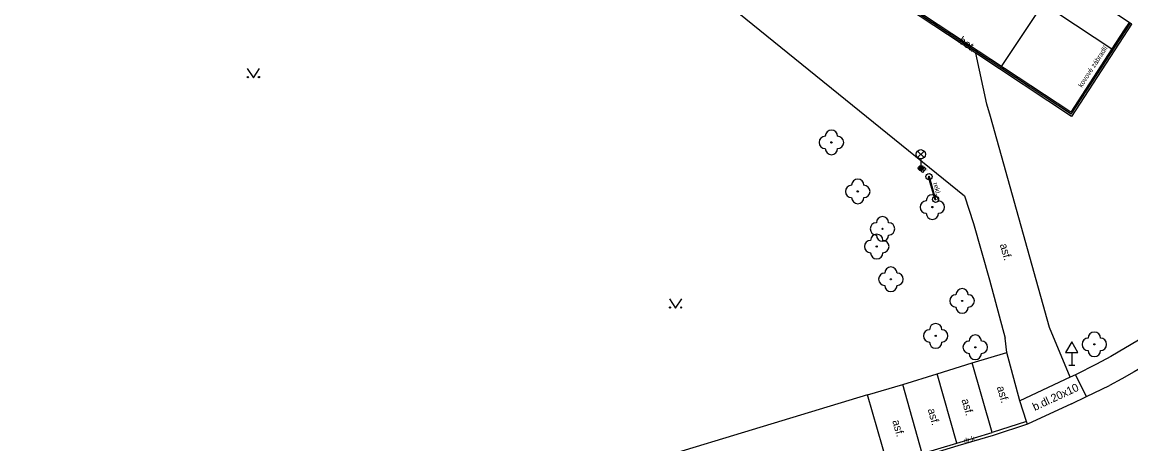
# Model space of a CAD drawing. Extents: x -598233 to -596890, y -1157848 to -1156431.
# Drawn here: x -597129.4 to -597039.3, y -1157222.9 to -1157188.6 of the extents above; entities that cross this region are included whole.
import ezdxf

# ---------------------------------------------------------------- set-up
doc = ezdxf.new("R2010")
doc.units = 0
for name, color, linetype in [('Level 10', 7, 'Continuous'), ('Level 11', 7, 'Continuous'), ('Level 22', 7, 'Continuous'), ('Level 25', 7, 'Continuous'), ('Level 33', 7, 'Continuous'), ('Level 34', 7, 'Continuous'), ('Level 36', 7, 'Continuous'), ('Level 40', 7, 'Continuous'), ('Level 42', 7, 'Continuous'), ('Level 5', 7, 'Continuous'), ('Level 7', 7, 'Continuous'), ('Level 9', 7, 'Continuous')]:
    doc.layers.add(name, color=color, linetype=linetype)

msp = doc.modelspace()

# ---------------------------------------------------------------- linework, layer by layer
at = {"layer": 'Level 10'}
for points in [[(-597060.71, -1157218.89), (-597057.85, -1157218.05), (-597055.05, -1157217.18), (-597052.2, -1157216.29), (-597049.38, -1157215.44)], [(-597044.13, -1157219.62), (-597047.7, -1157221.27), (-597047.78, -1157221.03), (-597048.32, -1157219.36), (-597049.38, -1157215.44)], [(-597038.06, -1157216.43), (-597039.05, -1157217.01), (-597040.04, -1157217.57), (-597041.05, -1157218.12)], [(-597044.13, -1157219.62), (-597042.91, -1157219.01), (-597041.05, -1157218.12)], [(-597060.71, -1157218.89), (-597086.42, -1157226.67), (-597120.23, -1157237.01)]]:
    msp.add_lwpolyline(points, dxfattribs=at)
at = {"layer": 'Level 11'}
for points in [[(-597144.73, -1157124.44), (-597135.06, -1157131.08), (-597109.67, -1157149.04), (-597101.08, -1157155.85), (-597100.46, -1157157.26), (-597101.39, -1157159.08), (-597101.51, -1157160.7), (-597101.1599, -1157162.15), (-597100.42, -1157163.42), (-597099.45, -1157164.7), (-597098.03, -1157166.15), (-597052.84, -1157202.74), (-597052.1, -1157204.97)], [(-597044.13, -1157196.28), (-597051.9, -1157191.16), (-597073.42, -1157176.98), (-597094.27, -1157163.14), (-597089.29, -1157155.68)], [(-597090.51, -1157157.96), (-597077.69, -1157166.4), (-597066.07, -1157174.11), (-597054.01, -1157182.08), (-597040.86, -1157190.8)], [(-597039.25, -1157188.79), (-597044.13, -1157196.28)], [(-597045.91, -1157213.41), (-597050.72, -1157196.29), (-597051, -1157195.3), (-597051.9, -1157191.16)], [(-597056.23, -1157200.84), (-597056.6, -1157200.5), (-597056.33, -1157200.28), (-597055.98, -1157200.5), (-597056.23, -1157200.84)], [(-597055.71, -1157201.17), (-597055.77, -1157201.19), (-597055.24, -1157203.03), (-597055.18, -1157203.02)], [(-597052.1, -1157204.97), (-597050.8, -1157209.55), (-597049.52, -1157214.29)], [(-597044.25, -1157217.44), (-597045.91, -1157213.41)], [(-597049.38, -1157215.44), (-597049.52, -1157214.29)], [(-597038.68, -1157214.45), (-597040.94, -1157215.78), (-597042.1, -1157216.39)], [(-597050.58, -1157221.93), (-597052.2, -1157216.29)], [(-597042.1, -1157216.39), (-597043.81, -1157217.25), (-597044.25, -1157217.44)], [(-597053.44, -1157222.79), (-597055.05, -1157217.18)], [(-597044.25, -1157217.44), (-597048.32, -1157219.36)], [(-597042.91, -1157219.01), (-597043.81, -1157217.25)], [(-597056.27, -1157223.65), (-597057.85, -1157218.05)], [(-597059.01, -1157224.75), (-597059.08, -1157224.51), (-597060.71, -1157218.89)], [(-597047.7, -1157221.27), (-597050.51, -1157222.17), (-597053.37, -1157223.03), (-597056.2, -1157223.89), (-597059.01, -1157224.75)], [(-597047.78, -1157221.03), (-597050.58, -1157221.93)], [(-597059.08, -1157224.51), (-597056.27, -1157223.65), (-597053.44, -1157222.79), (-597050.58, -1157221.93)]]:
    msp.add_lwpolyline(points, dxfattribs=at)
at = {"layer": 'Level 22'}
for centre in [(-597063.64, -1157198.39), (-597061.5, -1157202.37), (-597055.44, -1157203.64), (-597059.49, -1157205.41), (-597059.96, -1157206.84), (-597058.81, -1157209.5), (-597053.02, -1157211.26), (-597055.17, -1157214.09), (-597051.95, -1157215.02), (-597042.28, -1157214.78)]:
    msp.add_circle(centre, 0.05, dxfattribs=at)
for centre, start, end in [((-597064.14, -1157198.39), 90, 270), ((-597063.64, -1157197.89), 0, 180), ((-597063.14, -1157198.39), 270, 90), ((-597063.64, -1157198.89), 180, 0), ((-597061.5, -1157201.87), 0, 180), ((-597062, -1157202.37), 90, 270), ((-597061, -1157202.37), 270, 90), ((-597055.44, -1157203.14), 0, 180), ((-597061.5, -1157202.87), 180, 0), ((-597055.94, -1157203.64), 90, 270), ((-597054.94, -1157203.64), 270, 90), ((-597059.49, -1157204.91), 0, 180), ((-597055.44, -1157204.14), 180, 0), ((-597059.99, -1157205.41), 90, 270), ((-597058.99, -1157205.41), 270, 90), ((-597059.96, -1157206.34), 0, 180), ((-597059.49, -1157205.91), 180, 0), ((-597060.46, -1157206.84), 90, 270), ((-597059.46, -1157206.84), 270, 90), ((-597059.96, -1157207.34), 180, 0), ((-597058.81, -1157209), 0, 180), ((-597059.31, -1157209.5), 90, 270), ((-597058.31, -1157209.5), 270, 90), ((-597058.81, -1157210), 180, 0), ((-597053.52, -1157211.26), 90, 270), ((-597053.02, -1157210.76), 0, 180), ((-597052.52, -1157211.26), 270, 90), ((-597053.02, -1157211.76), 180, 0), ((-597055.17, -1157213.59), 0, 180), ((-597055.67, -1157214.09), 90, 270), ((-597054.67, -1157214.09), 270, 90), ((-597051.95, -1157214.52), 0, 180), ((-597042.78, -1157214.78), 90, 270), ((-597042.28, -1157214.28), 0, 180), ((-597041.78, -1157214.78), 270, 90), ((-597055.17, -1157214.59), 180, 0), ((-597052.45, -1157215.02), 90, 270), ((-597051.45, -1157215.02), 270, 90), ((-597051.95, -1157215.52), 180, 0), ((-597042.28, -1157215.28), 180, 0)]:
    msp.add_arc(centre, 0.5, start, end, dxfattribs=at)
at = {"layer": 'Level 25'}
msp.add_lwpolyline([(-597055.71, -1157201.17), (-597055.18, -1157203.02)], dxfattribs=at)
for centre, radius in [((-597055.71, -1157201.17), 0.25), ((-597055.71, -1157201.17), 0.0303), ((-597055.18, -1157203.02), 0.25), ((-597055.18, -1157203.02), 0.0303)]:
    msp.add_circle(centre, radius, dxfattribs=at)
at = {"layer": 'Level 33'}
for p, q in [((-597056.645, -1157199.62), (-597056.115, -1157199.09)), ((-597056.645, -1157199.09), (-597056.115, -1157199.62)), ((-597056.38, -1157199.73), (-597056.38, -1157200.48))]:
    msp.add_line(p, q, dxfattribs=at)
for centre, radius in [((-597056.38, -1157199.355), 0.375), ((-597056.38, -1157200.48), 0.2), ((-597056.38, -1157200.48), 0.1445), ((-597056.38, -1157200.48), 0.0876)]:
    msp.add_circle(centre, radius, dxfattribs=at)
at = {"layer": 'Level 34'}
for p, q in [((-597044.11, -1157215.442), (-597044.11, -1157216.46)), ((-597044.36, -1157216.46), (-597043.86, -1157216.46))]:
    msp.add_line(p, q, dxfattribs=at)
msp.add_lwpolyline([(-597044.61, -1157215.442), (-597043.61, -1157215.442), (-597044.11, -1157214.576)], close=True, dxfattribs=at)
at = {"layer": 'Level 36'}
for points in [[(-597111.1, -1157192.39), (-597110.6, -1157193.14), (-597110.1, -1157192.39)], [(-597076.8, -1157211.09), (-597076.3, -1157211.84), (-597075.8, -1157211.09)]]:
    msp.add_lwpolyline(points, dxfattribs=at)
for centre in [(-597111.0502, -1157193.0898), (-597110.1508, -1157193.0898), (-597076.7502, -1157211.7898), (-597075.8508, -1157211.7898)]:
    msp.add_circle(centre, 0.05, dxfattribs=at)
at = {"layer": 'Level 5'}
msp.add_lwpolyline([(-597039.22, -1157188.81), (-597039.25, -1157188.79), (-597039.46, -1157188.65), (-597041.66, -1157187.19)], dxfattribs=at)
at = {"layer": 'Level 7'}
for points in [[(-597044.2, -1157195.93), (-597073.28, -1157176.77), (-597093.92, -1157163.07), (-597090.51, -1157157.96)], [(-597039.46, -1157188.65), (-597039.85, -1157189.25), (-597040.86, -1157190.8), (-597044.2, -1157195.93)]]:
    msp.add_lwpolyline(points, dxfattribs=at)
at = {"layer": 'Level 9'}
for points in [[(-597044.16, -1157196.1), (-597073.35, -1157176.87), (-597094.09, -1157163.1), (-597089.18, -1157155.75)], [(-597049.83, -1157192.22), (-597045, -1157184.98)], [(-597044.16, -1157196.1), (-597039.35, -1157188.72)]]:
    msp.add_lwpolyline(points, dxfattribs=at)

# ---------------------------------------------------------------- texts
at = {"layer": 'Level 40'}
for s, height, rotation, p in [('bet.', 0.65, 325.885527, (-597053.36, -1157190.27)), ('asf.', 0.65, 285.919372, (-597049.97, -1157206.69)), ('b.dl.20x10', 0.65, 24.805666, (-597047.12, -1157220.19)), ('asf.', 0.65, 286.035443, (-597050.21, -1157218.26)), ('asf.', 0.65, 286.02298, (-597053.08, -1157219.29)), ('asf.', 0.65, 285.776803, (-597055.83, -1157220.07)), ('asf.', 0.65, 285.776803, (-597058.7, -1157221)), ('dr.k.', 0.4, 16.735996, (-597052.83, -1157222.83))]:
    msp.add_text(s, height=height, rotation=rotation, dxfattribs=at).set_placement(p)
msp.add_text('b.', height=0.4, dxfattribs=at).set_placement((-597056.27, -1157200.67))
at = {"layer": 'Level 42'}
for s, rotation, p in [('kovové zábradlí', 57, (-597043.29, -1157193.97)), ('rekl.', 285.986292, (-597055.4, -1157201.71))]:
    msp.add_text(s, height=0.4, rotation=rotation, dxfattribs=at).set_placement(p)

doc.saveas('drawing.dxf')
